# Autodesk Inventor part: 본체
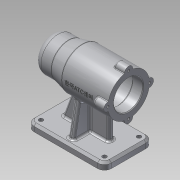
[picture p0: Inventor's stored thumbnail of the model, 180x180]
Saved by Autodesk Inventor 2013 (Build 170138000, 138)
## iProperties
Created: 2019-07
Part Number: 본체
Material: 알루미늄 6061
Document SubType Name: Modeling
Designer: Administrator
Density: 2.71 g/cm^3
Mass: 646.451 g
Surface Area: 654.972 cm^2
Volume: 238.543 cm^3
Author: Administrator
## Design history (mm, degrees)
sketch "스케치1"
  geometry: L1 (-56, 0)-(56, 0); L2 (-56, 0)-(-56, 25); L3 (-56, 25)-(-31, 25); L4 (-31, 25)-(-11, 30); L5 (-11, 30)-(56, 30); L6 (56, 30)-(56, 21); L7 (56, 21)-(41, 21); L8 (41, 21)-(41, 24); L9 (41, 24)-(-13, 24); L10 (-13, 24)-(-13, 21); L11 (-13, 21)-(-25, 21); L12 (-25, 21)-(-25, 17.5); L13 (-25, 17.5)-(-43, 17.5); L14 (-43, 17.5)-(-43, 16); L15 (-43, 16)-(-47, 16); L16 (-47, 16)-(-47, 10.5); L17 (-47, 10.5)-(-50, 10.5); L18 (-50, 10.5)-(-50, 0); 2 further points
  constraints: 36 end point, 9 horizontal, 8 vertical, 2 coincident, 1 collinear, 1 midpoint, 1 point on line, 1 vertical alignment
  dimensions: "d0" = 112 distance of L1.start L1.end; "d2" = 21 diameter of L17 L1; "d3" = 32 diameter of L15 L1; "d4" = 35 diameter of L13 L1; "d5" = 42 diameter of L11 L1; "d6" = 48 diameter of L9 L1; "d7" = 15 distance of L6.end L7.end; "d9" = 4 distance of L14.end L15.end; "d10" = 3 distance of L16.end L17.end; "d11" = 18 distance of L12.end L13.end; "d12" = 12 distance of L10.end L11.end; "d13" = 54 distance of L8.end L9.end; "d14" = 45 distance from line of L4.end L2; "d15" = 25 distance of L2.end L3.end; "d16" = 50 diameter of L3 L1; "d17" = 60 diameter of L5 L1
revolve "회전1" sketch "스케치1" stored, may be unused: angle "d18" = 90 deg
fillet "모깎기1" dims "d19" = 10
sketch "스케치2"
  geometry: C1 r 6 at (0, 30); 2 further points
  constraints: 1 centre point, 1 coincident, 1 vertical alignment, 1 other
  dimensions: "d20" = 12 diameter of C1
extrude "돌출1" join sketch "스케치2" distance "d22" = 16; taper "d23" = 0 deg
hole "구멍1" sketch "스케치2" diameter "d24" = 3.242; stored, may be unused: countersink angle "d28" = 90 deg, drill point angle "d30" = 118 deg; dims "d25" = 8, "d26" = 4, "d27" = 2, "d29" = 11
node "작업 평면1"
sketch "스케치3"
  geometry: L1 (-56, -35)-(56, -35); L2 (56, -35)-(56, 35); L3 (56, 35)-(-56, 35); L4 (-56, 35)-(-56, -35); L5 (-56, -35)-(56, 35); L6 (56, -35)-(-56, 35); 1 further point
  constraints: 12 end point, 2 midpoint, 2 parallel, 1 horizontal, 1 perpendicular
  dimensions: "d35" = 112 distance of L2.end L3.end; "d37" = 70 distance of L1.end L2.end
extrude "돌출2" join sketch "스케치3" distance "d38" = 10; taper "d39" = 0 deg
fillet "모깎기2" dims "d40" = 10
sketch "스케치4"
  geometry: L1 (-46, -25)-(46, -25); L2 (46, -25)-(46, 25); L3 (46, 25)-(-46, 25); L4 (-46, 25)-(-46, -25); L5 (-46, -25)-(46, 25); L6 (46, -25)-(-46, 25); 5 further points
  constraints: 12 end point, 4 coincident, 2 midpoint, 2 parallel, 1 horizontal, 1 perpendicular
  dimensions: "d41" = 92 distance of L2.end L3.end; "d43" = 50 distance of L3.end L1.start
hole "구멍2" sketch "스케치4" at (-46, 25), (-46, -25), (46, -25), (46, 25) diameter "d44" = 6; stored, may be unused: countersink angle "d48" = 90 deg, drill point angle "d50" = 118 deg; dims "d45" = 8, "d46" = 4, "d47" = 2, "d49" = 25
sketch "스케치5"
  geometry: L1 (-56, 25)-(-56, -25) reference; L2 (56, -25)-(56, 25) reference; L3 (46, 35)-(-46, 35) reference; L4 (-4, -28)-(4, -28); L5 (4, -28)-(4, 28); L6 (4, 28)-(-4, 28); L7 (-4, 28)-(-4, -28); L8 (-4, -28)-(4, 28); L9 (4, -28)-(-4, 28); L10 (-36, 4)-(31, 4); L11 (31, 4)-(31, -4); L12 (31, -4)-(-36, -4); L13 (-36, -4)-(-36, 4); 3 further points
  constraints: 20 end point, 4 midpoint, 4 parallel, 3 perpendicular, 2 horizontal, 1 horizontal alignment
  dimensions: "d51" = 20 distance between parallel lines of L13 L1; "d52" = 25 distance between parallel lines of L2 L11; "d53" = 8 distance of L5.end L6.end; "d54" = 7 distance between parallel lines of L6 L3
extrude "돌출3" join sketch "스케치5" stored distance "d55" = 10; taper "d56" = 0 deg
feature "면 기울기1" dims angle "d57" = 20 deg
fillet "모깎기5" dims "d60" = 0.3
chamfer "모따기1" distance "d61" = 3; stored, may be unused: second distance "d62" = 2, angle "d63" = 45 deg
feature "면 기울기2" dims angle "d64" = 10 deg
fillet "모깎기6" dims "d65" = 3
fillet "모깎기7" dims "d66" = 3
fillet "모깎기8" dims "d67" = 1
node "작업 평면3"
sketch "스케치7"
  geometry: L1 (33.5, 36)-(33.5, 30.171) reference; 2 further points
  constraints: 1 horizontal alignment, 1 other
  dimensions: "d68" = 42 distance from line of point (-8.5, 0) L1
feature "엠보싱1" sketch "스케치7" dims "d0" = 112, "d2" = 21, "d3" = 32, "d4" = 35, "d5" = 42, "d6" = 48, "d7" = 15, "d9" = 4, "d10" = 3, "d11" = 18, "d12" = 12, "d13" = 54, "d14" = 45, "d15" = 25, "d16" = 50, "d17" = 60, "d69" = 0.5, "d70" = 0
chamfer "모따기2" distance "d71" = 1; stored, may be unused: second distance "d72" = 2, angle "d73" = 45 deg
node "솔리드1"
pattern_circular "원형 패턴1" dims angle "d32" = 360 deg
